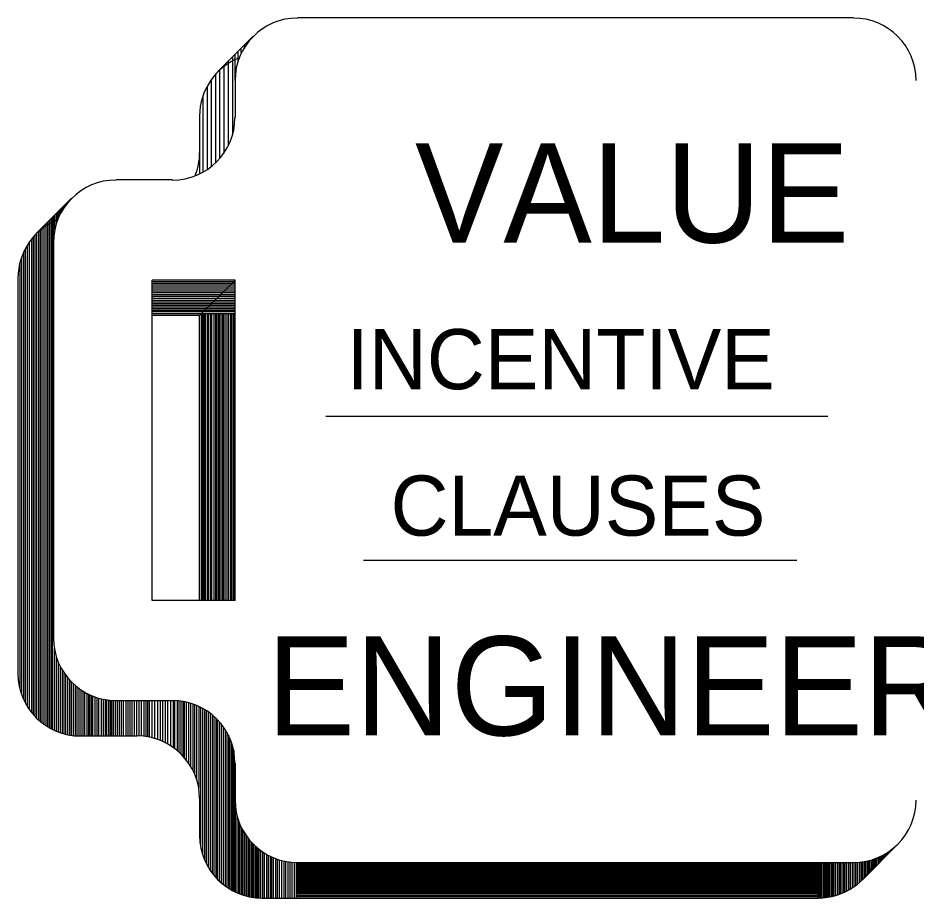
# Model space of a CAD drawing. Extents: x 22422.9 to 22498.9, y 22369.6 to 22415.
# Drawn here: x 22443.407 to 22444.604, y 22371.331 to 22372.503 of the extents above; entities that cross this region are included whole.
import ezdxf

# ---------------------------------------------------------------- set-up
doc = ezdxf.new("R2010")
doc.units = 0
doc.layers.add('Level 2', color=7, linetype='Continuous')
doc.layers.add('Level 7', color=7, linetype='Continuous')

msp = doc.modelspace()

# ---------------------------------------------------------------- linework, layer by layer
at = {"layer": 'Level 2'}
for p, q in [((22443.6734, 22372.432), (22443.7205, 22372.4792)), ((22443.7087, 22372.464), (22443.7087, 22372.4673)), ((22443.7122, 22372.4693), (22443.7122, 22372.4708)), ((22443.6962, 22372.4202), (22443.6962, 22372.4548)), ((22443.7002, 22372.4457), (22443.7002, 22372.4588)), ((22443.7045, 22372.4565), (22443.7045, 22372.4632)), ((22443.6872, 22372.4458), (22443.6872, 22372.3333)), ((22443.6929, 22372.4515), (22443.6929, 22372.3477)), ((22443.6755, 22372.4342), (22443.6755, 22372.316)), ((22443.6812, 22372.4398), (22443.6812, 22372.3233)), ((22443.6644, 22372.4212), (22443.6644, 22372.3055)), ((22443.67, 22372.4283), (22443.67, 22372.3103)), ((22443.6592, 22372.4128), (22443.6592, 22372.3017)), ((22443.6535, 22372.4), (22443.6535, 22372.2983)), ((22443.649, 22372.373), (22443.649, 22372.296)), ((22443.4314, 22372.2162), (22443.4785, 22372.2633)), ((22443.465, 22372.2455), (22443.465, 22372.2498)), ((22443.4667, 22372.2482), (22443.4667, 22372.2515)), ((22443.4684, 22372.2508), (22443.4684, 22372.2532)), ((22443.47, 22372.2532), (22443.47, 22372.2548)), ((22443.4524, 22372.2372), (22443.4524, 22371.5563)), ((22443.4542, 22372.2043), (22443.4542, 22372.239)), ((22443.456, 22372.2217), (22443.456, 22372.2408)), ((22443.4584, 22372.2303), (22443.4584, 22372.2432)), ((22443.4602, 22372.2353), (22443.4602, 22372.245)), ((22443.4619, 22372.2392), (22443.4619, 22372.2467)), ((22443.4634, 22372.2423), (22443.4634, 22372.2482)), ((22443.4414, 22372.2262), (22443.4414, 22371.5632)), ((22443.4442, 22372.229), (22443.4442, 22371.5612)), ((22443.4465, 22372.2313), (22443.4465, 22371.5597)), ((22443.4487, 22372.2335), (22443.4487, 22371.5583)), ((22443.4509, 22372.2357), (22443.4509, 22371.5572)), ((22443.4294, 22372.214), (22443.4294, 22371.5737)), ((22443.4317, 22372.2163), (22443.4317, 22371.5713)), ((22443.4345, 22372.2193), (22443.4345, 22371.5687)), ((22443.4365, 22372.2213), (22443.4365, 22371.5668)), ((22443.4387, 22372.2235), (22443.4387, 22371.5652)), ((22443.422, 22372.2048), (22443.422, 22371.5828)), ((22443.4249, 22372.2087), (22443.4249, 22371.579)), ((22443.4272, 22372.2115), (22443.4272, 22371.5762)), ((22443.4145, 22372.1917), (22443.4145, 22371.596)), ((22443.4167, 22372.1962), (22443.4167, 22371.5915)), ((22443.4194, 22372.2008), (22443.4194, 22371.5868)), ((22443.4119, 22372.1852), (22443.4119, 22371.6025)), ((22443.4094, 22372.1767), (22443.4094, 22371.611)), ((22443.407, 22372.1572), (22443.407, 22371.6305)), ((22443.6962, 22372.1543), (22443.649, 22372.1072)), ((22443.6962, 22372.1522), (22443.5859, 22372.1522)), ((22443.6962, 22372.15), (22443.5859, 22372.15)), ((22443.6962, 22372.1475), (22443.5859, 22372.1475)), ((22443.6962, 22372.145), (22443.5859, 22372.145)), ((22443.6962, 22372.1423), (22443.5859, 22372.1423)), ((22443.6962, 22372.1398), (22443.5859, 22372.1398)), ((22443.6962, 22372.1373), (22443.5859, 22372.1373)), ((22443.6962, 22372.1347), (22443.5859, 22372.1347)), ((22443.6962, 22372.1323), (22443.5859, 22372.1323)), ((22443.6962, 22372.1298), (22443.5859, 22372.1298)), ((22443.6962, 22372.1273), (22443.5859, 22372.1273)), ((22443.6962, 22372.125), (22443.5859, 22372.125)), ((22443.6962, 22372.1227), (22443.5859, 22372.1227)), ((22443.6962, 22372.1207), (22443.5859, 22372.1207)), ((22443.6962, 22372.1182), (22443.5859, 22372.1182)), ((22443.6962, 22372.1162), (22443.5859, 22372.1162)), ((22443.6962, 22372.114), (22443.5859, 22372.114)), ((22443.6962, 22372.112), (22443.5859, 22372.112)), ((22443.6962, 22372.1095), (22443.5859, 22372.1095)), ((22443.649, 22372.1072), (22443.5859, 22372.1072)), ((22443.649, 22371.7277), (22443.649, 22372.1072)), ((22443.6514, 22371.7277), (22443.6514, 22372.1095)), ((22443.6532, 22371.7277), (22443.6532, 22372.1095)), ((22443.6552, 22371.7277), (22443.6552, 22372.1095)), ((22443.6569, 22371.7277), (22443.6569, 22372.1095)), ((22443.6594, 22371.7277), (22443.6594, 22372.1095)), ((22443.6615, 22371.7277), (22443.6615, 22372.1095)), ((22443.6639, 22371.7277), (22443.6639, 22372.1095)), ((22443.6655, 22371.7277), (22443.6655, 22372.1095)), ((22443.6682, 22371.7277), (22443.6682, 22372.1095)), ((22443.6704, 22371.7277), (22443.6704, 22372.1095)), ((22443.6722, 22371.7277), (22443.6722, 22372.1095)), ((22443.6744, 22371.7277), (22443.6744, 22372.1095)), ((22443.6765, 22371.7277), (22443.6765, 22372.1095)), ((22443.679, 22371.7277), (22443.679, 22372.1095)), ((22443.681, 22371.7277), (22443.681, 22372.1095)), ((22443.683, 22371.7277), (22443.683, 22372.1095)), ((22443.6855, 22371.7277), (22443.6855, 22372.1095)), ((22443.688, 22371.7277), (22443.688, 22372.1095)), ((22443.6905, 22371.7277), (22443.6905, 22372.1095)), ((22443.6922, 22371.7277), (22443.6922, 22372.1095)), ((22443.6944, 22371.7277), (22443.6944, 22372.1095)), ((22443.4554, 22371.6638), (22443.4554, 22371.5548)), ((22443.458, 22371.6527), (22443.458, 22371.5537)), ((22443.4605, 22371.6458), (22443.4605, 22371.5527)), ((22443.463, 22371.6403), (22443.463, 22371.5518)), ((22443.466, 22371.6348), (22443.466, 22371.5508)), ((22443.4682, 22371.6315), (22443.4682, 22371.5502)), ((22443.4704, 22371.6283), (22443.4704, 22371.5497)), ((22443.4732, 22371.6247), (22443.4732, 22371.549)), ((22443.4755, 22371.622), (22443.4755, 22371.5485)), ((22443.478, 22371.6193), (22443.478, 22371.5482)), ((22443.4805, 22371.6168), (22443.4805, 22371.5477)), ((22443.483, 22371.6147), (22443.483, 22371.5475)), ((22443.4854, 22371.6127), (22443.4854, 22371.5473)), ((22443.4882, 22371.6105), (22443.4882, 22371.5472)), ((22443.4907, 22371.6087), (22443.4907, 22371.5472)), ((22443.4932, 22371.6072), (22443.4932, 22371.5472)), ((22443.4957, 22371.6057), (22443.4957, 22371.5472)), ((22443.4987, 22371.604), (22443.4987, 22371.5472)), ((22443.5009, 22371.6028), (22443.5009, 22371.5472)), ((22443.5022, 22371.6022), (22443.5022, 22371.5472)), ((22443.5044, 22371.6012), (22443.5044, 22371.5472)), ((22443.5065, 22371.6003), (22443.5065, 22371.5472)), ((22443.5092, 22371.5993), (22443.5092, 22371.5472)), ((22443.5119, 22371.5983), (22443.5119, 22371.5472)), ((22443.5144, 22371.5977), (22443.5144, 22371.5472)), ((22443.5177, 22371.5967), (22443.5177, 22371.5472)), ((22443.5207, 22371.596), (22443.5207, 22371.5472)), ((22443.5232, 22371.5955), (22443.5232, 22371.5472)), ((22443.525, 22371.5953), (22443.525, 22371.5472)), ((22443.5275, 22371.595), (22443.5275, 22371.5472)), ((22443.5297, 22371.5947), (22443.5297, 22371.5472)), ((22443.5315, 22371.5945), (22443.5315, 22371.5472)), ((22443.5339, 22371.5943), (22443.5339, 22371.5472)), ((22443.5365, 22371.5943), (22443.5365, 22371.5472)), ((22443.539, 22371.5943), (22443.539, 22371.5472)), ((22443.5419, 22371.5943), (22443.5419, 22371.5472)), ((22443.5447, 22371.5943), (22443.5447, 22371.5472)), ((22443.5472, 22371.5943), (22443.5472, 22371.5472)), ((22443.5505, 22371.5943), (22443.5505, 22371.5472)), ((22443.5534, 22371.5943), (22443.5534, 22371.5472)), ((22443.5559, 22371.5943), (22443.5559, 22371.5472)), ((22443.5587, 22371.5943), (22443.5587, 22371.5472)), ((22443.5619, 22371.5943), (22443.5619, 22371.5472)), ((22443.5649, 22371.5943), (22443.5649, 22371.5472)), ((22443.568, 22371.5943), (22443.568, 22371.5472)), ((22443.5712, 22371.5943), (22443.5712, 22371.5472)), ((22443.5749, 22371.5943), (22443.5749, 22371.5467)), ((22443.5774, 22371.5943), (22443.5774, 22371.5463)), ((22443.5795, 22371.5943), (22443.5795, 22371.546)), ((22443.5817, 22371.5943), (22443.5817, 22371.5457)), ((22443.5852, 22371.5943), (22443.5852, 22371.5448)), ((22443.5889, 22371.5943), (22443.5889, 22371.5438)), ((22443.5927, 22371.5943), (22443.5927, 22371.5427)), ((22443.5964, 22371.5943), (22443.5964, 22371.5413)), ((22443.5995, 22371.5943), (22443.5995, 22371.54)), ((22443.6032, 22371.5943), (22443.6032, 22371.5383)), ((22443.606, 22371.5943), (22443.606, 22371.5368)), ((22443.6104, 22371.5943), (22443.6104, 22371.5342)), ((22443.6139, 22371.5943), (22443.6139, 22371.5318)), ((22443.6157, 22371.5943), (22443.6157, 22371.5305)), ((22443.6189, 22371.5943), (22443.6189, 22371.528)), ((22443.6214, 22371.5938), (22443.6214, 22371.5258)), ((22443.624, 22371.5935), (22443.624, 22371.5233)), ((22443.6265, 22371.5932), (22443.6265, 22371.5208)), ((22443.6284, 22371.5928), (22443.6284, 22371.5188)), ((22443.6312, 22371.5923), (22443.6312, 22371.5153)), ((22443.634, 22371.5917), (22443.634, 22371.5115)), ((22443.637, 22371.5908), (22443.637, 22371.5068)), ((22443.6399, 22371.5898), (22443.6399, 22371.5018)), ((22443.6424, 22371.589), (22443.6424, 22371.4965)), ((22443.645, 22371.5878), (22443.645, 22371.4893)), ((22443.6479, 22371.5867), (22443.6479, 22371.4777)), ((22443.65, 22371.5857), (22443.65, 22371.4018)), ((22443.6527, 22371.5842), (22443.6527, 22371.3902)), ((22443.6554, 22371.5827), (22443.6554, 22371.3828)), ((22443.6579, 22371.5812), (22443.6579, 22371.3773)), ((22443.6604, 22371.5795), (22443.6604, 22371.3727)), ((22443.6629, 22371.5777), (22443.6629, 22371.3687)), ((22443.6657, 22371.5755), (22443.6657, 22371.3647)), ((22443.6679, 22371.5737), (22443.6679, 22371.3618)), ((22443.6704, 22371.5713), (22443.6704, 22371.359)), ((22443.6725, 22371.5692), (22443.6725, 22371.3567)), ((22443.6752, 22371.5663), (22443.6752, 22371.354)), ((22443.6777, 22371.5633), (22443.6777, 22371.3518)), ((22443.6805, 22371.5597), (22443.6805, 22371.3493)), ((22443.6832, 22371.5557), (22443.6832, 22371.3473)), ((22443.4904, 22371.5472), (22443.5657, 22371.5472)), ((22443.6854, 22371.5522), (22443.6854, 22371.3458)), ((22443.6874, 22371.5483), (22443.6874, 22371.3445)), ((22443.689, 22371.5448), (22443.689, 22371.3435)), ((22443.6912, 22371.5395), (22443.6912, 22371.3422)), ((22443.693, 22371.5338), (22443.693, 22371.3412)), ((22443.6945, 22371.5275), (22443.6945, 22371.3403)), ((22443.649, 22371.4638), (22443.649, 22371.4147)), ((22443.6964, 22371.4565), (22443.6964, 22371.3395)), ((22443.6987, 22371.4415), (22443.6987, 22371.3385)), ((22443.7009, 22371.4343), (22443.7009, 22371.3375)), ((22443.7027, 22371.4295), (22443.7027, 22371.3368)), ((22443.7047, 22371.4252), (22443.7047, 22371.336)), ((22443.7064, 22371.422), (22443.7064, 22371.3355)), ((22443.7087, 22371.418), (22443.7087, 22371.3348)), ((22443.7109, 22371.4147), (22443.7109, 22371.3342)), ((22443.7132, 22371.4113), (22443.7132, 22371.3335)), ((22443.7149, 22371.4093), (22443.7149, 22371.3332)), ((22443.7172, 22371.4065), (22443.7172, 22371.3327)), ((22443.7185, 22371.405), (22443.7185, 22371.3325)), ((22443.7204, 22371.4032), (22443.7204, 22371.3322)), ((22443.7224, 22371.4012), (22443.7224, 22371.332)), ((22443.7239, 22371.3998), (22443.7239, 22371.3318)), ((22444.532, 22371.3557), (22444.5792, 22371.4028)), ((22443.7249, 22371.399), (22443.7249, 22371.3317)), ((22443.726, 22371.398), (22443.726, 22371.3315)), ((22443.7279, 22371.3965), (22443.7279, 22371.3315)), ((22443.7302, 22371.3947), (22443.7302, 22371.3315)), ((22443.7329, 22371.3928), (22443.7329, 22371.3315)), ((22443.7352, 22371.3913), (22443.7352, 22371.3315)), ((22443.7379, 22371.3897), (22443.7379, 22371.3315)), ((22443.7404, 22371.3883), (22443.7404, 22371.3315)), ((22444.5594, 22371.383), (22444.5594, 22371.3883)), ((22444.5609, 22371.3845), (22444.5609, 22371.3892)), ((22444.5624, 22371.386), (22444.5624, 22371.39)), ((22444.564, 22371.3877), (22444.564, 22371.391)), ((22444.5657, 22371.3893), (22444.5657, 22371.392)), ((22444.5672, 22371.3908), (22444.5672, 22371.393)), ((22444.5687, 22371.3923), (22444.5687, 22371.394)), ((22444.5702, 22371.3938), (22444.5702, 22371.3952)), ((22443.7429, 22371.387), (22443.7429, 22371.3315)), ((22443.7449, 22371.386), (22443.7449, 22371.3315)), ((22443.7472, 22371.385), (22443.7472, 22371.3315)), ((22443.7499, 22371.384), (22443.7499, 22371.3315)), ((22443.7525, 22371.383), (22443.7525, 22371.3315)), ((22443.7552, 22371.3822), (22443.7552, 22371.3315)), ((22443.758, 22371.3813), (22443.758, 22371.3315)), ((22443.761, 22371.3805), (22443.761, 22371.3315)), ((22443.7634, 22371.38), (22443.7634, 22371.3315)), ((22443.7664, 22371.3795), (22443.7664, 22371.3315)), ((22443.769, 22371.3792), (22443.769, 22371.3315)), ((22443.7717, 22371.3788), (22443.7717, 22371.3315)), ((22443.7749, 22371.3787), (22443.7749, 22371.3315)), ((22443.7775, 22371.3785), (22443.7775, 22371.3315)), ((22443.7775, 22371.3773), (22444.473, 22371.3773)), ((22443.7775, 22371.3765), (22444.473, 22371.3765)), ((22443.7775, 22371.3757), (22444.473, 22371.3757)), ((22444.473, 22371.3313), (22444.473, 22371.3785)), ((22444.4749, 22371.3313), (22444.4749, 22371.3785)), ((22444.4762, 22371.3313), (22444.4762, 22371.3785)), ((22444.4775, 22371.3315), (22444.4775, 22371.3785)), ((22444.4797, 22371.3317), (22444.4797, 22371.3785)), ((22444.4814, 22371.3318), (22444.4814, 22371.3785)), ((22444.4834, 22371.332), (22444.4834, 22371.3785)), ((22444.485, 22371.3322), (22444.485, 22371.3785)), ((22444.4869, 22371.3325), (22444.4869, 22371.3785)), ((22444.4884, 22371.3328), (22444.4884, 22371.3785)), ((22444.4904, 22371.3332), (22444.4904, 22371.3785)), ((22444.4922, 22371.3335), (22444.4922, 22371.3785)), ((22444.494, 22371.334), (22444.494, 22371.3785)), ((22444.4964, 22371.3347), (22444.4964, 22371.3785)), ((22444.4989, 22371.3355), (22444.4989, 22371.3785)), ((22444.5009, 22371.3362), (22444.5009, 22371.3785)), ((22444.5029, 22371.3368), (22444.5029, 22371.3785)), ((22444.505, 22371.3377), (22444.505, 22371.3785)), ((22444.5072, 22371.3387), (22444.5072, 22371.3785)), ((22444.509, 22371.3395), (22444.509, 22371.3785)), ((22444.5115, 22371.3408), (22444.5115, 22371.3785)), ((22444.514, 22371.3422), (22444.514, 22371.3785)), ((22444.5164, 22371.3435), (22444.5164, 22371.3785)), ((22444.5187, 22371.345), (22444.5187, 22371.3785)), ((22444.521, 22371.3465), (22444.521, 22371.3785)), ((22444.5232, 22371.3482), (22444.5232, 22371.3785)), ((22444.5255, 22371.35), (22444.5255, 22371.3785)), ((22444.528, 22371.352), (22444.528, 22371.3788)), ((22444.5304, 22371.3542), (22444.5304, 22371.3792)), ((22444.5324, 22371.356), (22444.5324, 22371.3793)), ((22444.5345, 22371.3582), (22444.5345, 22371.3797)), ((22444.5362, 22371.3598), (22444.5362, 22371.38)), ((22444.5382, 22371.3618), (22444.5382, 22371.3805)), ((22444.5399, 22371.3635), (22444.5399, 22371.3808)), ((22444.5417, 22371.3653), (22444.5417, 22371.3813)), ((22444.5437, 22371.3673), (22444.5437, 22371.3818)), ((22444.545, 22371.3687), (22444.545, 22371.3823)), ((22444.5467, 22371.3703), (22444.5467, 22371.3828)), ((22444.5482, 22371.3718), (22444.5482, 22371.3833)), ((22444.5499, 22371.3735), (22444.5499, 22371.384)), ((22444.5509, 22371.3745), (22444.5509, 22371.3843)), ((22444.5529, 22371.3765), (22444.5529, 22371.3852)), ((22444.5544, 22371.378), (22444.5544, 22371.3858)), ((22444.556, 22371.3797), (22444.556, 22371.3867)), ((22444.5579, 22371.3815), (22444.5579, 22371.3875)), ((22443.7775, 22371.3745), (22444.473, 22371.3745)), ((22443.7775, 22371.3732), (22444.473, 22371.3732)), ((22443.7775, 22371.3717), (22444.473, 22371.3717)), ((22443.7775, 22371.3702), (22444.473, 22371.3702)), ((22443.7775, 22371.3688), (22444.473, 22371.3688)), ((22443.7775, 22371.3673), (22444.473, 22371.3673)), ((22443.7775, 22371.3658), (22444.473, 22371.3658)), ((22443.7775, 22371.3643), (22444.473, 22371.3643)), ((22443.7775, 22371.3628), (22444.473, 22371.3628)), ((22443.7775, 22371.3613), (22444.473, 22371.3613)), ((22443.7775, 22371.36), (22444.473, 22371.36)), ((22443.7775, 22371.3585), (22444.473, 22371.3585)), ((22443.7775, 22371.3572), (22444.473, 22371.3572)), ((22443.7775, 22371.3558), (22444.473, 22371.3558)), ((22443.7775, 22371.3543), (22444.473, 22371.3543)), ((22443.7775, 22371.3528), (22444.473, 22371.3528)), ((22443.7775, 22371.3512), (22444.473, 22371.3512)), ((22443.7775, 22371.3495), (22444.473, 22371.3495)), ((22443.7775, 22371.3478), (22444.473, 22371.3478)), ((22443.7775, 22371.3463), (22444.473, 22371.3463)), ((22443.7775, 22371.3445), (22444.473, 22371.3445)), ((22443.7775, 22371.3428), (22444.473, 22371.3428)), ((22443.7775, 22371.341), (22444.473, 22371.341)), ((22443.7324, 22371.3313), (22444.473, 22371.3313)), ((22443.7775, 22371.3392), (22444.473, 22371.3392)), ((22443.7775, 22371.3372), (22444.473, 22371.3372)), ((22443.7775, 22371.3353), (22444.473, 22371.3353)), ((22443.7775, 22371.3335), (22444.473, 22371.3335))]:
    msp.add_line(p, q, dxfattribs=at)
for centre, start, end in [((22443.7323, 22372.3729), 111.4079, 180), ((22443.5657, 22372.3238), 338.5921, 0), ((22443.4903, 22372.1571), 111.4079, 180), ((22443.4903, 22371.6304), 180, 270), ((22443.5657, 22371.4638), 0, 90), ((22443.7323, 22371.4146), 180, 270), ((22444.473, 22371.4146), 270, 338.5921)]:
    msp.add_arc(centre, 0.0833, start, end, dxfattribs=at)
at = {"layer": 'Level 7'}
for p, q in [((22444.5202, 22372.5035), (22443.7795, 22372.5035)), ((22443.6962, 22372.4202), (22443.6962, 22372.371)), ((22443.6129, 22372.2877), (22443.5375, 22372.2877)), ((22443.4542, 22372.2043), (22443.4542, 22371.6777)), ((22443.6962, 22372.1543), (22443.5859, 22372.1543)), ((22443.5859, 22371.7277), (22443.5859, 22372.1543)), ((22443.6962, 22371.7277), (22443.6962, 22372.1543)), ((22443.817, 22371.9732), (22444.4862, 22371.9732)), ((22443.8674, 22371.7812), (22444.4449, 22371.7812)), ((22443.6962, 22371.7277), (22443.5859, 22371.7277)), ((22443.5375, 22371.5943), (22443.6129, 22371.5943)), ((22443.6962, 22371.511), (22443.6962, 22371.4618)), ((22443.7795, 22371.3785), (22444.5202, 22371.3785))]:
    msp.add_line(p, q, dxfattribs=at)
for centre, start, end in [((22443.7795, 22372.4201), 90, 180), ((22444.5202, 22372.4201), 0, 90), ((22443.6128, 22372.3709), 270, 0), ((22443.5375, 22372.2043), 90, 180), ((22443.5375, 22371.6776), 180, 270), ((22443.6128, 22371.5109), 0, 90), ((22443.7795, 22371.4618), 180, 270), ((22444.5202, 22371.4618), 270, 0)]:
    msp.add_arc(centre, 0.0833, start, end, dxfattribs=at)

# ---------------------------------------------------------------- texts
at = {"layer": 'Level 2'}
for s, height, p in [('VALUE', 0.13199, (22443.936, 22372.2043)), ('INCENTIVE', 0.08, (22443.8447, 22372.009)), ('CLAUSES', 0.08, (22443.9034, 22371.814)), ('ENGINEERING', 0.13199, (22443.7384, 22371.5478))]:
    msp.add_text(s, height=height, dxfattribs=at).set_placement(p)

doc.saveas('drawing.dxf')
